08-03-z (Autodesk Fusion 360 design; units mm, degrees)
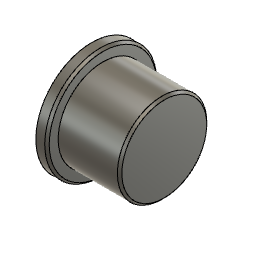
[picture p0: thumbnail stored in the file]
sketch "スケッチ" plane through (0, 0, 0) normal (0, 0, 1) x axis (1, 0, 0)
  line L1 (0, 5) -> (0, 0)
  line L2 (1, 5) -> (0, 5)
  line L3 (1, 4) -> (1, 5)
  line L4 (6.5, 4) -> (1, 4)
  line L5 (6.5, 0) -> (6.5, 4)
  line L6 (0, 0) -> (6.5, 0)
  point P1 (0, 0)
  point P2 (0, 0)
  point P8 (0, 0)
  point P3 (0, 5)
  point P4 (1, 5)
  point P5 (1, 4)
  point P6 (6.5, 4)
  coincident P1 P2
  vertical L1
  perpendicular L1 L2
  perpendicular L2 L3
  perpendicular L3 L4
  perpendicular L2 L5
  coincident P1 P8
  horizontal L6
  dimension "d1" = 10
  dimension "d2" = 8
  dimension "d3" distance P3 P4 = 1
  dimension "d4" distance P5 P6 = 5.5
revolve "回転" sketch "スケッチ" AlongAngle 360
chamfer "面取り" distance 0.2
